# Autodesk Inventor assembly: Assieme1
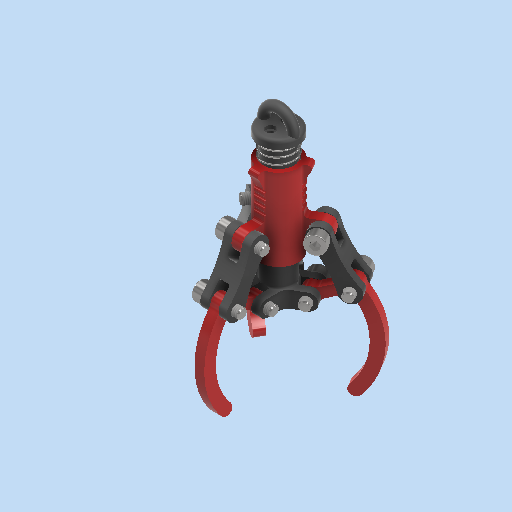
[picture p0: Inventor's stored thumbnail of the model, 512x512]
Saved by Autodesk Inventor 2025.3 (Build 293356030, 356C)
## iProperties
Created: 2026-05
Part Number: Assieme1
Document SubType Name: Assembly
Designer: Ryzen5700u
Author: Ryzen5700u
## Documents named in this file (9)
- C:\Users\R5800u\Desktop\portachiavi\Assieme1.iam
- C:\Users\R5800u\Desktop\portachiavi\Parte1.ipt
- C:\Users\R5800u\Desktop\portachiavi\Parte3.ipt
- C:\Users\R5800u\Desktop\portachiavi\Parte2.ipt
- C:\Users\R5800u\Desktop\portachiavi\Parte4.ipt
- C:\Users\R5800u\Documents\Inventor\Content Center Files\R2025\it-IT\AS 1420\AS 1420 - 1973 - M3 x 10.ipt
- C:\Users\R5800u\Desktop\portachiavi\Molla di compressione11.ipt
- C:\Users\R5800u\Desktop\portachiavi\Parte5.ipt
- C:\Users\R5800u\Desktop\portachiavi\vite.ipt
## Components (20 placed, 8 different names)
1. Parte1:1 — Coincidente:1, Coincidente:4, Coincidente:5, Angolo:1
2. Parte3:1 — Coincidente:1, Coincidente:2, Coincidente:3, Angolo:1, Rotazionale:1, Rotazionale:3, Rotazionale:5, Coincidente:9, Coincidente:10, Coincidente:11, Coincidente:12
3. AS 1420 - Metrico M3 x 10:2 — Rotazionale:1
4. AS 1420 - Metrico M3 x 10:3 — Rotazionale:2
5. AS 1420 - Metrico M3 x 10:4 — Rotazionale:3
6. AS 1420 - Metrico M3 x 10:5 — Rotazionale:4
7. AS 1420 - Metrico M3 x 10:6 — Rotazionale:5
8. AS 1420 - Metrico M3 x 10:7 — Rotazionale:6
9. AS 1420 - Metrico M3 x 10:9 — Rotazionale:9
10. AS 1420 - Metrico M3 x 10:10 — Rotazionale:7
11. AS 1420 - Metrico M3 x 10:11 — Rotazionale:10
12. Molla di compressione1:1 — Coincidente:11, Coincidente:12
13. Parte5:1 — Coincidente:9, Coincidente:10, Angolo:2
14. vite:1 — Rotazionale:11
15. Parte4:1 — Coincidente:4, Coincidente:5, Coincidente:6, Rotazionale:6, Rotazionale:10
16. Parte2:1 — Coincidente:2, Coincidente:3, Coincidente:6
17. Parte4:2 — Rotazionale:2, Rotazionale:7
18. Parte2:2
19. Parte4:3 — Rotazionale:4, Rotazionale:9, Rotazionale:11
20. Parte2:3
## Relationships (22: Mate 10, RevoluteJoint 10, Angle 2)
- Coincidente:1 [Mate]: Parte1:1 ↔ Parte3:1
- Coincidente:2 [Mate]: Parte3:1 ↔ Parte2:1
- Coincidente:3 [Mate]: Parte3:1 ↔ Parte2:1
- Coincidente:4 [Mate]: Parte1:1 ↔ Parte4:1
- Coincidente:5 [Mate]: Parte1:1 ↔ Parte4:1
- Coincidente:6 [Mate]: Parte4:1 ↔ Parte2:1
- Angolo:1 [Angle]: Parte1:1 ↔ Parte3:1
- Rotazionale:1 [RevoluteJoint]: Parte3:1 ↔ AS 1420 - Metrico M3 x 10:2
- Rotazionale:2 [RevoluteJoint]: AS 1420 - Metrico M3 x 10:3 ↔ Parte4:2
- Rotazionale:3 [RevoluteJoint]: Parte3:1 ↔ AS 1420 - Metrico M3 x 10:4
- Rotazionale:4 [RevoluteJoint]: AS 1420 - Metrico M3 x 10:5 ↔ Parte4:3
- Rotazionale:5 [RevoluteJoint]: Parte3:1 ↔ AS 1420 - Metrico M3 x 10:6
- Rotazionale:6 [RevoluteJoint]: AS 1420 - Metrico M3 x 10:7 ↔ Parte4:1
- Rotazionale:7 [RevoluteJoint]: AS 1420 - Metrico M3 x 10:10 ↔ Parte4:2
- Rotazionale:9 [RevoluteJoint]: AS 1420 - Metrico M3 x 10:9 ↔ Parte4:3
- Rotazionale:10 [RevoluteJoint]: AS 1420 - Metrico M3 x 10:11 ↔ Parte4:1
- Coincidente:9 [Mate]: Parte3:1 ↔ Parte5:1
- Coincidente:10 [Mate]: Parte3:1 ↔ Parte5:1
- Angolo:2 [Angle]: Parte5:1
- Rotazionale:11 [RevoluteJoint]: vite:1 ↔ Parte4:3
- Coincidente:11 [Mate]: Parte3:1 ↔ Molla di compressione1:1
- Coincidente:12 [Mate]: Parte3:1 ↔ Molla di compressione1:1
